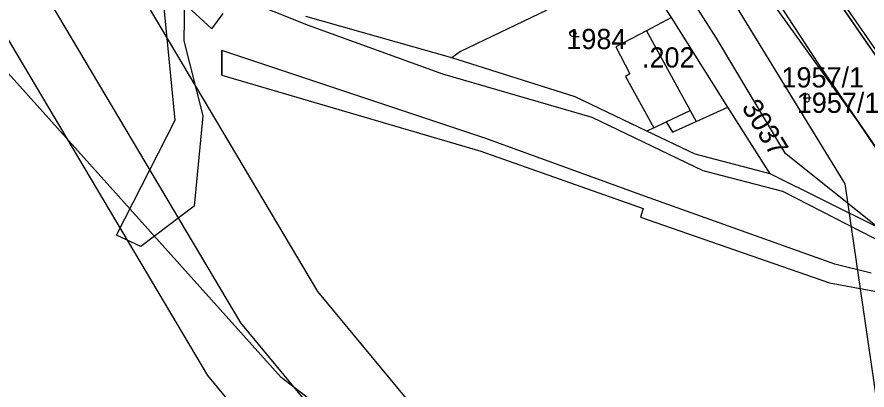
# Model space of a CAD drawing. Extents: x -564810 to -550519, y -1045831 to -1034011.
# Drawn here: x -553048.4 to -552833.7, y -1038095.3 to -1038001.2 of the extents above; entities that cross this region are included whole.
import ezdxf

# ---------------------------------------------------------------- set-up
doc = ezdxf.new("R2010")
doc.units = 0
for name, color, linetype in [('KN stav', 7, 'Continuous'), ('Obvod KPU', 7, 'Continuous'), ('Parcelní čísla', 7, 'Continuous'), ('Plynovod', 7, 'Continuous'), ('Polní cesty stavající', 7, 'Continuous'), ('přeložka st silnice', 7, 'Continuous'), ('STG', 7, 'Continuous'), ('Vrstva 22', 7, 'Continuous'), ('Vrstva 39', 7, 'Continuous'), ('Vrstva 4', 7, 'Continuous'), ('zamokř ploch', 7, 'Continuous')]:
    doc.layers.add(name, color=color, linetype=linetype)

msp = doc.modelspace()

# ---------------------------------------------------------------- linework, layer by layer
at = {"layer": 'KN stav'}
for p, q in [((-552856.25, -1037973.85), (-552779.12, -1038085.41)), ((-552845.85, -1038013.14), (-552868.15, -1037979.06)), ((-553008.44, -1038027.28), (-553012.61, -1037984.23)), ((-552884.49, -1037986.79), (-552871.75, -1038006.55)), ((-553005.89, -1037988.07), (-553006.21, -1038007.25)), ((-552883.09, -1038001.34), (-552891.43, -1037988.5)), ((-552914.54, -1037999.5), (-552936.32, -1038009.88)), ((-552938.57, -1038011.54), (-552975.43, -1038001.08)), ((-552883.09, -1038001.34), (-552889.36, -1038004.69)), ((-552868.8, -1038023.96), (-552883.09, -1038001.34)), ((-552889.36, -1038004.69), (-552897.15, -1038008.73)), ((-553006.21, -1038007.25), (-553001.44, -1038026.16)), ((-552871.75, -1038006.55), (-552854.55, -1038035.44)), ((-552936.32, -1038009.88), (-552938.57, -1038011.54)), ((-552897.15, -1038008.73), (-552893.57, -1038015.55)), ((-552907.41, -1038021.37), (-552938.57, -1038011.54)), ((-552811.12, -1038063.66), (-552845.85, -1038013.14)), ((-552893.57, -1038015.55), (-552894.71, -1038016.2)), ((-552894.71, -1038016.2), (-552887.56, -1038029.22)), ((-552889.26, -1038030.06), (-552907.41, -1038021.37)), ((-552858.19, -1038040.76), (-552868.8, -1038023.96)), ((-553023.26, -1038056.27), (-553008.44, -1038027.28)), ((-553001.44, -1038026.16), (-553003.59, -1038048.95)), ((-552887.56, -1038029.22), (-552889.26, -1038030.06)), ((-552877.13, -1038035.8), (-552889.26, -1038030.06)), ((-552858.19, -1038040.76), (-552877.13, -1038035.8)), ((-552854.55, -1038035.44), (-552830.68, -1038054.43)), ((-552830.68, -1038054.43), (-552858.19, -1038040.76)), ((-553003.59, -1038048.95), (-553017.05, -1038059.09)), ((-553017.05, -1038059.09), (-553023.26, -1038056.27))]:
    msp.add_line(p, q, dxfattribs=at)
at = {"layer": 'Obvod KPU'}
for p, q in [((-552863.09, -1037965.02), (-552799.7, -1038057.26)), ((-552974.77, -1038003.35), (-552996.15, -1037994.79)), ((-552940.85, -1038015.62), (-552974.77, -1038003.35)), ((-552903.1, -1038026.61), (-552940.85, -1038015.62)), ((-552875.05, -1038040.03), (-552903.1, -1038026.61)), ((-552854.97, -1038045.25), (-552875.05, -1038040.03)), ((-552828.06, -1038059.06), (-552854.97, -1038045.25))]:
    msp.add_line(p, q, dxfattribs=at)
at = {"layer": 'Plynovod'}
for points in [[(-554428.56, -1035578.55), (-554428.56, -1035578.55), (-554428.56, -1035578.55), (-554027.79, -1036081.22), (-553723.76, -1036467.01), (-553550.38, -1036705.78), (-553550.38, -1036705.78), (-553522.74, -1037110.43), (-553438.57, -1037242.38), (-553213.69, -1037591.73), (-553193.58, -1037703.57), (-553145.84, -1037777.72), (-553110.67, -1037838.04), (-552972.47, -1038070.52), (-552972.47, -1038070.52), (-552302.85, -1038878.56)], [(-552322.24, -1038886.46), (-552991.86, -1038078.43), (-553130.06, -1037845.94), (-553165.24, -1037785.62), (-553212.98, -1037711.48), (-553233.08, -1037599.64), (-553457.96, -1037250.28), (-553542.14, -1037118.33), (-553569.78, -1036713.69), (-553743.15, -1036474.92), (-554047.18, -1036089.12), (-554447.95, -1035586.45)], [(-552330.5, -1038899.71), (-553000.12, -1038091.67), (-553138.32, -1037859.19), (-553173.5, -1037798.87), (-553221.24, -1037724.72), (-553241.34, -1037612.88), (-553466.22, -1037263.53), (-553550.4, -1037131.58), (-553578.03, -1036726.93), (-553751.41, -1036488.16), (-554055.44, -1036102.37), (-554456.21, -1035599.7)]]:
    msp.add_lwpolyline(points, dxfattribs=at)
at = {"layer": 'Polní cesty stavající'}
for p, q in [((-553006.25, -1037997.74), (-552999.17, -1038004.19)), ((-552999.17, -1038004.19), (-552996.26, -1038000.34)), ((-552996.59, -1038015.85), (-552996.59, -1038009.7)), ((-552930.19, -1038031.81), (-552996.59, -1038009.7)), ((-552996.59, -1038009.7), (-552996.59, -1038015.85)), ((-552996.59, -1038015.85), (-552931.2, -1038035.11)), ((-552888.72, -1038046.85), (-552930.19, -1038031.81)), ((-552931.2, -1038035.11), (-552890.21, -1038049.5)), ((-552841.83, -1038063.56), (-552888.72, -1038046.85)), ((-552890.21, -1038049.5), (-552890.9, -1038051.7)), ((-552890.9, -1038051.7), (-552843.15, -1038068.33)), ((-552832.62, -1038065.9), (-552841.83, -1038063.56)), ((-552843.15, -1038068.33), (-552831.31, -1038070.49))]:
    msp.add_line(p, q, dxfattribs=at)
at = {"layer": 'přeložka st silnice'}
msp.add_lwpolyline([(-552359.45, -1038509.27), (-552838.68, -1038201.82), (-552981.64, -1038092.23), (-553086.65, -1037975.23), (-553204.95, -1037781.11), (-553324.39, -1037500.52), (-553448.24, -1037281.74), (-553591.55, -1037076.57), (-553686.12, -1036910.24), (-553749.25, -1036695.02), (-553795.26, -1036480.46), (-553954.63, -1036164.34)], dxfattribs=at)
at = {"layer": 'STG'}
msp.add_lwpolyline([(-553073.05, -1038865.18), (-553035.76, -1038846.34), (-553000.85, -1038835.32), (-552975.13, -1038807.75), (-552969.62, -1038761.81), (-552964.11, -1038682.8), (-552954.92, -1038625.83), (-552942.06, -1038576.22), (-552931.04, -1038508.22), (-552905.32, -1038432.88), (-552885.11, -1038375.92), (-552846.53, -1038289.55), (-552826.33, -1038206.86), (-552826.33, -1038131.52), (-552839.19, -1038043.31), (-552883.28, -1037971.28), (-552936.55, -1037903.29), (-552991.66, -1037859.19), (-553035.76, -1037837.14), (-553038.14, -1037823.26)], dxfattribs=at)
at = {"layer": 'Vrstva 39'}
for points in [[(-552959.84, -1037829.57), (-552949.38, -1037836.64), (-552943.1, -1037850.43), (-552889.95, -1037926.5), (-552826.14, -1038018.72), (-552786.78, -1038074.05), (-552775.94, -1038089.37), (-552767.17, -1038099.82), (-552754.39, -1038113.88), (-552707.18, -1038164.11)], [(-552717.19, -1038172.67), (-552764.4, -1038122.36), (-552780.41, -1038105.99), (-552799, -1038088.05), (-552805.72, -1038081.97), (-552816.39, -1038067.13), (-552810.23, -1038064.91), (-552813.1, -1038061.43), (-552835.83, -1038027.74), (-552856.82, -1037998.61), (-552858.48, -1037995.56), (-552897.12, -1037940.43)]]:
    msp.add_lwpolyline(points, dxfattribs=at)
at = {"layer": 'Vrstva 4'}
for p, q in [((-552889.36, -1038004.69), (-552878.34, -1038024.79)), ((-552884.38, -1038027.69), (-552878.34, -1038024.79)), ((-552878.34, -1038024.79), (-552876.81, -1038027.57)), ((-552876.81, -1038027.57), (-552868.8, -1038023.96)), ((-552887.56, -1038029.22), (-552884.38, -1038027.69)), ((-552884.38, -1038027.69), (-552882.8, -1038030.28)), ((-552882.8, -1038030.28), (-552876.81, -1038027.57))]:
    msp.add_line(p, q, dxfattribs=at)
at = {"layer": 'zamokř ploch'}
for p, q in [((-552907.99, -1038006.1), (-552906.39, -1038006.1)), ((-552849.3, -1038022.15), (-552849.3, -1038021.15)), ((-552848.3, -1038021.15), (-552848.3, -1038022.15)), ((-552849.8, -1038021.65), (-552847.8, -1038021.65))]:
    msp.add_line(p, q, dxfattribs=at)
msp.add_circle((-552907.99, -1038005.35), 0.75, dxfattribs=at)
for centre, start, end in [((-552848.8, -1038021.15), 0, 180), ((-552848.8, -1038022.15), 180, 0)]:
    msp.add_arc(centre, 0.5, start, end, dxfattribs=at)

# ---------------------------------------------------------------- texts
at = {"layer": 'Parcelní čísla'}
for s, p in [('1984', (-552909.62, -1038009.31)), ('1957/1', (-552855.3, -1038018.99)), ('1957/1', (-552851.43, -1038025.4))]:
    msp.add_text(s, height=5.1, dxfattribs=at).set_placement(p)
msp.add_text('3037', height=5.1, rotation=301.0271, dxfattribs=at).set_placement((-552865.48, -1038023.95))
at = {"layer": 'Vrstva 22'}
msp.add_text('.202', height=5.1, dxfattribs=at).set_placement((-552890.52, -1038013.96))

doc.saveas('drawing.dxf')
